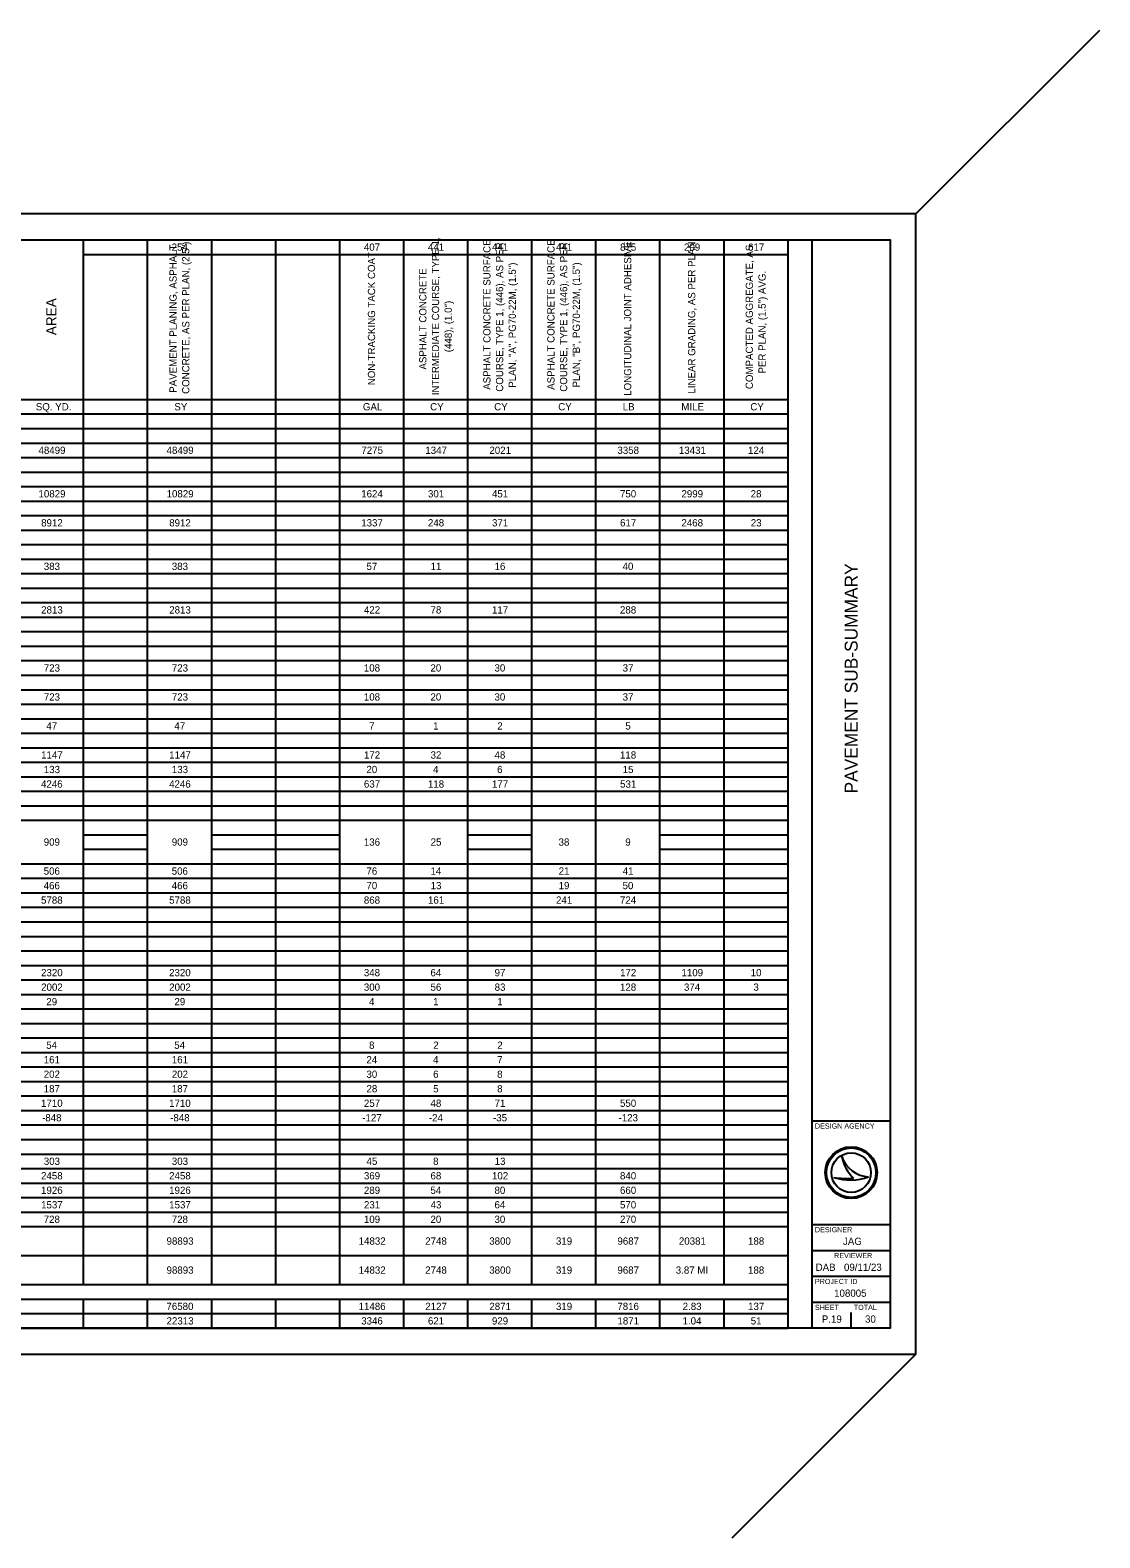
# Model space of a CAD drawing. Extents: x 768 to 809.1, y -451.7 to -422.6.
# Drawn here: x 788.48 to 809.12, y -451.72 to -422.62 of the extents above; entities that cross this region are included whole.
import ezdxf

# ---------------------------------------------------------------- set-up
doc = ezdxf.new("R2010")
doc.units = 0
for name, color, linetype in [('Level 11', 7, 'Continuous'), ('SC_Scratch1', 7, 'Continuous'), ('SH_Border', 7, 'Continuous'), ('SH_Cut_Line', 7, 'Continuous'), ('SH_Data', 7, 'Continuous')]:
    doc.layers.add(name, color=color, linetype=linetype)

msp = doc.modelspace()

# ---------------------------------------------------------------- linework, layer by layer
at = {"layer": 'Level 11'}
for p, q in [((773.069, -426.67), (803.094, -426.67)), ((789.506, -426.67), (789.506, -446.83)), ((790.741, -426.67), (790.741, -446.83)), ((791.977, -426.67), (791.977, -446.83)), ((793.212, -426.67), (793.212, -446.83)), ((794.447, -426.67), (794.447, -446.83)), ((795.683, -426.67), (795.683, -446.83)), ((796.918, -426.67), (796.918, -446.83)), ((798.153, -426.67), (798.153, -446.83)), ((799.389, -426.67), (799.389, -446.83)), ((800.624, -426.67), (800.624, -446.83)), ((801.859, -426.67), (801.859, -446.83)), ((803.094, -426.67), (803.094, -447.67)), ((789.506, -426.95), (803.094, -426.95)), ((776.083, -429.75), (803.094, -429.75)), ((773.069, -430.03), (803.094, -430.03)), ((783.33, -430.31), (803.094, -430.31)), ((773.069, -430.59), (803.094, -430.59)), ((773.069, -430.87), (803.094, -430.87)), ((773.069, -431.15), (803.094, -431.15)), ((773.069, -431.43), (803.094, -431.43)), ((773.069, -431.71), (803.094, -431.71)), ((773.069, -431.99), (803.094, -431.99)), ((773.069, -432.27), (803.094, -432.27)), ((773.069, -432.55), (803.094, -432.55)), ((773.069, -432.83), (803.094, -432.83)), ((773.069, -433.11), (803.094, -433.11)), ((773.069, -433.39), (803.094, -433.39)), ((773.069, -433.67), (803.094, -433.67)), ((773.069, -433.95), (803.094, -433.95)), ((773.069, -434.23), (803.094, -434.23)), ((773.069, -434.51), (803.094, -434.51)), ((773.069, -434.79), (803.094, -434.79)), ((773.069, -435.07), (803.094, -435.07)), ((773.069, -435.35), (803.094, -435.35)), ((773.069, -435.63), (803.094, -435.63)), ((773.069, -435.91), (803.094, -435.91)), ((773.069, -436.19), (803.094, -436.19)), ((773.069, -436.47), (803.094, -436.47)), ((773.069, -436.75), (803.094, -436.75)), ((773.069, -437.03), (803.094, -437.03)), ((773.069, -437.31), (803.094, -437.31)), ((773.069, -437.59), (803.094, -437.59)), ((773.069, -437.87), (803.094, -437.87)), ((789.506, -438.15), (790.741, -438.15)), ((791.977, -438.15), (794.447, -438.15)), ((796.918, -438.15), (798.153, -438.15)), ((800.624, -438.15), (803.094, -438.15)), ((789.506, -438.43), (790.741, -438.43)), ((791.977, -438.43), (794.447, -438.43)), ((796.918, -438.43), (798.153, -438.43)), ((800.624, -438.43), (803.094, -438.43)), ((773.069, -438.71), (803.094, -438.71)), ((773.069, -438.99), (803.094, -438.99)), ((773.069, -439.27), (803.094, -439.27)), ((773.069, -439.55), (803.094, -439.55)), ((773.069, -439.83), (803.094, -439.83)), ((773.069, -440.11), (803.094, -440.11)), ((773.069, -440.39), (803.094, -440.39)), ((773.069, -440.67), (803.094, -440.67)), ((773.069, -440.95), (803.094, -440.95)), ((773.069, -441.23), (803.094, -441.23)), ((773.069, -441.51), (803.094, -441.51)), ((773.069, -441.79), (803.094, -441.79)), ((773.069, -442.07), (803.094, -442.07)), ((773.069, -442.35), (803.094, -442.35)), ((773.069, -442.63), (803.094, -442.63)), ((773.069, -442.91), (803.094, -442.91)), ((773.069, -443.19), (803.094, -443.19)), ((773.069, -443.47), (803.094, -443.47)), ((773.069, -443.75), (803.094, -443.75)), ((773.069, -444.03), (803.094, -444.03)), ((773.069, -444.31), (803.094, -444.31)), ((773.069, -444.59), (803.094, -444.59)), ((773.069, -444.87), (803.094, -444.87)), ((773.069, -445.15), (803.094, -445.15)), ((773.069, -445.43), (803.094, -445.43)), ((773.069, -445.71), (803.094, -445.71)), ((773.069, -446.27), (803.094, -446.27)), ((773.069, -446.83), (803.094, -446.83)), ((773.069, -447.11), (803.094, -447.11)), ((789.506, -447.11), (789.506, -447.67)), ((790.741, -447.11), (790.741, -447.67)), ((791.977, -447.11), (791.977, -447.67)), ((793.212, -447.11), (793.212, -447.67)), ((794.447, -447.11), (794.447, -447.67)), ((795.683, -447.11), (795.683, -447.67)), ((796.918, -447.11), (796.918, -447.67)), ((798.153, -447.11), (798.153, -447.67)), ((799.389, -447.11), (799.389, -447.67)), ((800.624, -447.11), (800.624, -447.67)), ((801.859, -447.11), (801.859, -447.67)), ((773.069, -447.39), (803.094, -447.39)), ((773.069, -447.67), (803.094, -447.67))]:
    msp.add_line(p, q, dxfattribs=at)
at = {"layer": 'SC_Scratch1'}
for p, q in [((805.569, -426.17), (809.115, -422.623)), ((802.022, -451.717), (805.569, -448.17))]:
    msp.add_line(p, q, dxfattribs=at)
at = {"layer": 'SH_Border'}
for p, q in [((803.569, -447.67), (803.569, -426.67)), ((803.569, -443.67), (805.069, -443.67)), ((803.569, -445.67), (805.069, -445.67)), ((803.569, -446.17), (805.069, -446.17)), ((803.569, -446.67), (805.069, -446.67)), ((803.569, -447.17), (805.069, -447.17))]:
    msp.add_line(p, q, dxfattribs=at)
msp.add_lwpolyline([(773.069, -426.67), (805.069, -426.67), (805.069, -447.67), (773.069, -447.67)], close=True, dxfattribs=at)
at = {"layer": 'SH_Cut_Line'}
msp.add_lwpolyline([(771.569, -448.17), (805.569, -448.17), (805.569, -426.17), (771.569, -426.17)], close=True, dxfattribs=at)
at = {"layer": 'SH_Data'}
for p, q in [((804.136, -444.361), (804.136, -444.361)), ((804.136, -444.361), (804.136, -444.361)), ((803.986, -444.761), (803.986, -444.761)), ((803.986, -444.761), (803.986, -444.761)), ((804.319, -444.67), (804.319, -444.67)), ((804.656, -444.752), (804.656, -444.752)), ((804.656, -444.752), (804.656, -444.752)), ((804.319, -447.67), (804.319, -447.37)), ((803.944, -447.495), (803.944, -447.495))]:
    msp.add_line(p, q, dxfattribs=at)
for radius in [0.5, 0.5, 0.477, 0.477, 0.477, 0.477, 0.382, 0.382]:
    msp.add_circle((804.319, -444.67), radius, dxfattribs=at)
for centre, radius, start, end in [((804.684, -444.172), 0.58, 198.9257, 198.9319), ((804.915, -444.2), 0.796, 191.6379, 191.6421), ((804.684, -444.172), 0.58, 198.9319, 267.1657), ((804.915, -444.2), 0.796, 191.6421, 226.0947), ((804.684, -444.172), 0.58, 198.9257, 198.9319), ((804.915, -444.2), 0.796, 191.6379, 191.6421), ((804.684, -444.172), 0.58, 198.9319, 267.1657), ((804.915, -444.2), 0.796, 191.6421, 226.0947), ((804.308, -443.8), 1.013, 251.4576, 290.0832), ((804.308, -443.8), 1.013, 251.4576, 290.0832), ((804.216, -443.516), 1.266, 259.4964, 259.4995), ((804.308, -443.8), 1.013, 251.4527, 251.4576), ((804.216, -443.516), 1.266, 259.4995, 276.6672), ((804.216, -443.516), 1.266, 259.4964, 259.4995), ((804.308, -443.8), 1.013, 251.4527, 251.4576), ((804.216, -443.516), 1.266, 259.4995, 276.6672)]:
    msp.add_arc(centre, radius, start, end, dxfattribs=at)

# ---------------------------------------------------------------- texts
at = {"layer": 'Level 11'}
for s, height, p in [('PAVEMENT PLANING, ASPHALT ', 0.14, (791.307, -429.62)), ('CONCRETE, AS PER PLAN, (2.5")', 0.14, (791.552, -429.642)), ('INTERMEDIATE COURSE, TYPE 1, ', 0.14, (796.37, -429.669)), ('ASPHALT CONCRETE SURFACE ', 0.14, (797.361, -429.563)), ('COURSE, TYPE 1, (446), AS PER ', 0.14, (797.606, -429.6)), ('ASPHALT CONCRETE SURFACE ', 0.14, (798.596, -429.563)), ('COURSE, TYPE 1, (446), AS PER ', 0.14, (798.841, -429.6)), ('LONGITUDINAL JOINT ADHESIVE', 0.14, (800.076, -429.678)), ('LINEAR GRADING, AS PER PLAN', 0.14, (801.311, -429.637)), ('COMPACTED AGGREGATE, AS ', 0.14, (802.424, -429.55)), ('NON-TRACKING TACK COAT', 0.14, (795.135, -429.475)), ('ASPHALT CONCRETE ', 0.14, (796.125, -429.173)), ('PLAN, "A", PG70-22M, (1.5")', 0.14, (797.851, -429.523)), ('PLAN, "B", PG70-22M, (1.5")', 0.14, (799.086, -429.519)), ('PER PLAN, (1.5") AVG.', 0.14, (802.669, -429.249)), ('AREA', 0.196, (788.987, -428.51)), ('(448), (1.0")', 0.14, (796.615, -428.838))]:
    msp.add_text(s, height=height, rotation=90, dxfattribs=at).set_placement(p)
for s, p in [('254', (791.21, -426.88)), ('407', (794.918, -426.88)), ('441', (796.154, -426.88)), ('441', (797.389, -426.88)), ('441', (798.625, -426.88)), ('875', (799.86, -426.88)), ('209', (801.094, -426.88)), ('617', (802.33, -426.88)), ('SQ. YD.', (788.59, -429.96)), ('SY', (791.263, -429.96)), ('GAL', (794.9, -429.96)), ('CY', (796.197, -429.96)), ('CY', (797.432, -429.96)), ('CY', (798.668, -429.96)), ('LB', (799.912, -429.96)), ('MILE', (801.042, -429.96)), ('CY', (802.373, -429.96)), ('48499', (788.642, -430.8)), ('48499', (791.113, -430.8)), ('7275', (794.87, -430.8)), ('1347', (796.104, -430.8)), ('2021', (797.34, -430.8)), ('3358', (799.809, -430.8)), ('13431', (800.995, -430.8)), ('124', (802.329, -430.8)), ('10829', (788.642, -431.64)), ('10829', (791.113, -431.64)), ('1624', (794.867, -431.64)), ('301', (796.155, -431.64)), ('451', (797.39, -431.64)), ('750', (799.859, -431.64)), ('2999', (801.045, -431.64)), ('28', (802.38, -431.64)), ('8912', (788.693, -432.2)), ('8912', (791.163, -432.2)), ('1337', (794.868, -432.2)), ('248', (796.154, -432.2)), ('371', (797.39, -432.2)), ('617', (799.86, -432.2)), ('2468', (801.044, -432.2)), ('23', (802.382, -432.2)), ('383', (788.744, -433.04)), ('383', (791.214, -433.04)), ('57', (794.969, -433.04)), ('11', (796.205, -433.04)), ('16', (797.439, -433.04)), ('40', (799.909, -433.04)), ('2813', (788.693, -433.88)), ('2813', (791.164, -433.88)), ('422', (794.92, -433.88)), ('78', (796.204, -433.88)), ('117', (797.389, -433.88)), ('288', (799.859, -433.88)), ('723', (788.744, -435)), ('723', (791.214, -435)), ('108', (794.918, -435)), ('20', (796.203, -435)), ('30', (797.438, -435)), ('37', (799.91, -435)), ('723', (788.744, -435.56)), ('723', (791.214, -435.56)), ('108', (794.918, -435.56)), ('20', (796.203, -435.56)), ('30', (797.438, -435.56)), ('37', (799.91, -435.56)), ('47', (788.793, -436.12)), ('47', (791.263, -436.12)), ('7', (795.019, -436.12)), ('1', (796.255, -436.12)), ('2', (797.491, -436.12)), ('5', (799.962, -436.12)), ('1147', (788.692, -436.68)), ('1147', (791.163, -436.68)), ('172', (794.92, -436.68)), ('32', (796.205, -436.68)), ('48', (797.439, -436.68)), ('118', (799.859, -436.68)), ('133', (788.744, -436.96)), ('133', (791.214, -436.96)), ('20', (794.968, -436.96)), ('4', (796.253, -436.96)), ('6', (797.489, -436.96)), ('15', (799.911, -436.96)), ('4246', (788.691, -437.24)), ('4246', (791.162, -437.24)), ('637', (794.919, -437.24)), ('118', (796.154, -437.24)), ('177', (797.389, -437.24)), ('531', (799.861, -437.24)), ('909', (788.743, -438.36)), ('909', (791.213, -438.36)), ('136', (794.918, -438.36)), ('25', (796.206, -438.36)), ('38', (798.674, -438.36)), ('9', (799.961, -438.36)), ('506', (788.742, -438.92)), ('506', (791.212, -438.92)), ('76', (794.968, -438.92)), ('14', (796.203, -438.92)), ('21', (798.676, -438.92)), ('41', (799.911, -438.92)), ('466', (788.742, -439.2)), ('466', (791.212, -439.2)), ('70', (794.968, -439.2)), ('13', (796.206, -439.2)), ('19', (798.675, -439.2)), ('50', (799.909, -439.2)), ('5788', (788.691, -439.48)), ('5788', (791.162, -439.48)), ('868', (794.918, -439.48)), ('161', (796.155, -439.48)), ('241', (798.625, -439.48)), ('724', (799.858, -439.48)), ('2320', (788.691, -440.88)), ('2320', (791.161, -440.88)), ('348', (794.918, -440.88)), ('64', (796.203, -440.88)), ('97', (797.44, -440.88)), ('172', (799.861, -440.88)), ('1109', (801.045, -440.88)), ('10', (802.38, -440.88)), ('2002', (788.693, -441.16)), ('2002', (791.163, -441.16)), ('300', (794.918, -441.16)), ('56', (796.204, -441.16)), ('83', (797.441, -441.16)), ('128', (799.859, -441.16)), ('374', (801.093, -441.16)), ('3', (802.433, -441.16)), ('29', (788.793, -441.44)), ('29', (791.264, -441.44)), ('4', (795.018, -441.44)), ('1', (796.255, -441.44)), ('1', (797.491, -441.44)), ('54', (788.791, -442.28)), ('54', (791.261, -442.28)), ('8', (795.019, -442.28)), ('2', (796.256, -442.28)), ('2', (797.491, -442.28)), ('161', (788.743, -442.56)), ('161', (791.214, -442.56)), ('24', (794.967, -442.56)), ('4', (796.253, -442.56)), ('7', (797.49, -442.56)), ('202', (788.743, -442.84)), ('202', (791.214, -442.84)), ('30', (794.968, -442.84)), ('6', (796.254, -442.84)), ('8', (797.489, -442.84)), ('187', (788.742, -443.12)), ('187', (791.213, -443.12)), ('28', (794.969, -443.12)), ('5', (796.256, -443.12)), ('8', (797.489, -443.12)), ('1710', (788.691, -443.4)), ('1710', (791.161, -443.4)), ('257', (794.919, -443.4)), ('48', (796.204, -443.4)), ('71', (797.44, -443.4)), ('550', (799.859, -443.4)), ('-848', (788.711, -443.68)), ('-848', (791.182, -443.68)), ('-127', (794.888, -443.68)), ('-24', (796.172, -443.68)), ('-35', (797.41, -443.68)), ('-123', (799.831, -443.68)), ('303', (788.744, -444.52)), ('303', (791.214, -444.52)), ('45', (794.97, -444.52)), ('8', (796.254, -444.52)), ('13', (797.441, -444.52)), ('2458', (788.691, -444.8)), ('2458', (791.162, -444.8)), ('369', (794.919, -444.8)), ('68', (796.204, -444.8)), ('102', (797.39, -444.8)), ('840', (799.859, -444.8)), ('1926', (788.691, -445.08)), ('1926', (791.162, -445.08)), ('289', (794.919, -445.08)), ('54', (796.203, -445.08)), ('80', (797.438, -445.08)), ('660', (799.859, -445.08)), ('1537', (788.692, -445.36)), ('1537', (791.163, -445.36)), ('231', (794.92, -445.36)), ('43', (796.206, -445.36)), ('64', (797.438, -445.36)), ('570', (799.859, -445.36)), ('728', (788.742, -445.64)), ('728', (791.212, -445.64)), ('109', (794.919, -445.64)), ('20', (796.203, -445.64)), ('30', (797.438, -445.64)), ('270', (799.859, -445.64)), ('98893', (791.112, -446.06)), ('14832', (794.818, -446.06)), ('2748', (796.102, -446.06)), ('3800', (797.337, -446.06)), ('319', (798.624, -446.06)), ('9687', (799.809, -446.06)), ('20381', (800.995, -446.06)), ('188', (802.329, -446.06)), ('98893', (791.112, -446.62)), ('14832', (794.818, -446.62)), ('2748', (796.102, -446.62)), ('3800', (797.337, -446.62)), ('319', (798.624, -446.62)), ('9687', (799.809, -446.62)), ('3.87 MI', (800.935, -446.62)), ('188', (802.329, -446.62)), ('76580', (791.11, -447.32)), ('22313', (791.112, -447.6)), ('11486', (794.817, -447.32)), ('3346', (794.867, -447.6)), ('2127', (796.103, -447.32)), ('621', (796.154, -447.6)), ('2871', (797.339, -447.32)), ('929', (797.389, -447.6)), ('319', (798.624, -447.32)), ('7816', (799.808, -447.32)), ('1871', (799.81, -447.6)), ('2.83', (801.068, -447.32)), ('1.04', (801.066, -447.6)), ('137', (802.33, -447.32)), ('51', (802.381, -447.6))]:
    msp.add_text(s, height=0.14, dxfattribs=at).set_placement(p)
at = {"layer": 'SH_Data'}
msp.add_text('PAVEMENT SUB-SUMMARY', height=0.25, rotation=90, dxfattribs=at).set_placement((804.444, -437.352))
for s, height, p in [('DESIGN AGENCY', 0.1, (803.619, -443.82)), ('DESIGNER', 0.1, (803.619, -445.82)), ('JAG', 0.14, (804.161, -446.065)), ('REVIEWER', 0.1, (803.99, -446.32)), ('DAB', 0.14, (803.633, -446.565)), ('09/11/23', 0.14, (804.18, -446.565)), ('PROJECT ID', 0.1, (803.619, -446.82)), ('108005', 0.14, (803.99, -447.065)), ('SHEET', 0.1, (803.619, -447.32)), ('P.19', 0.14, (803.752, -447.565)), ('TOTAL', 0.1, (804.369, -447.32)), ('30', 0.14, (804.586, -447.565))]:
    msp.add_text(s, height=height, dxfattribs=at).set_placement(p)

doc.saveas('drawing.dxf')
